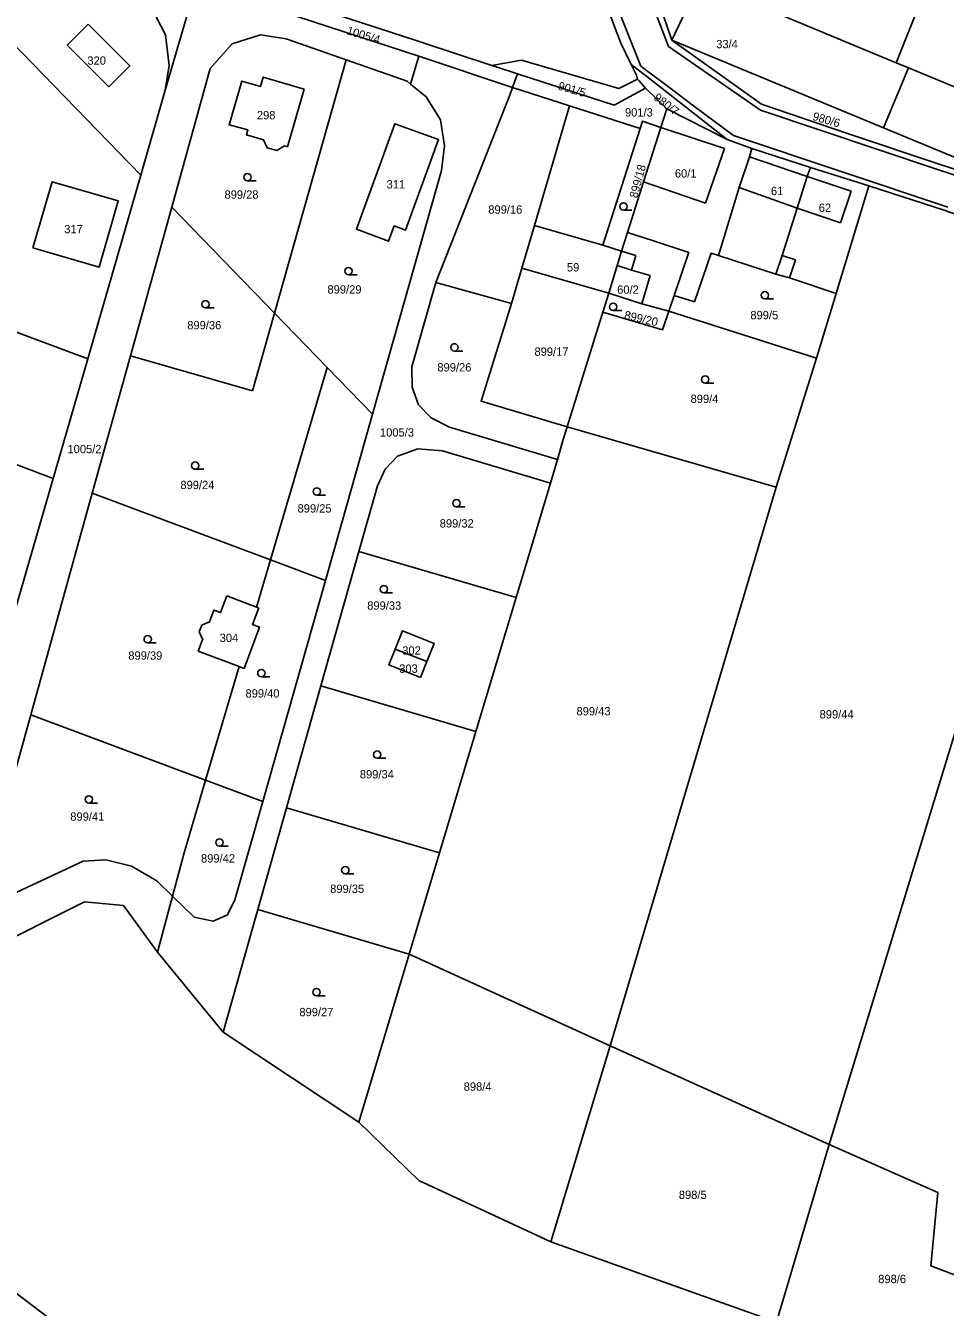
# Model space of a CAD drawing. Extents: x -7483133 to -743169, y -11317770 to -1127091.
# Drawn here: x -751107.9 to -750919.9, y -1131658.7 to -1131396.7 of the extents above; entities that cross this region are included whole.
import ezdxf

# ---------------------------------------------------------------- set-up
doc = ezdxf.new("R2010")
doc.units = 0
for name, color, linetype in [('Hranice parcel', 7, 'Continuous'), ('Parcelní čísla', 7, 'Continuous'), ('Vnitřní kresba', 7, 'Continuous'), ('Značky kultur', 7, 'Continuous')]:
    doc.layers.add(name, color=color, linetype=linetype)

msp = doc.modelspace()

# ---------------------------------------------------------------- linework, layer by layer
at = {"layer": 'Hranice parcel'}
for p, q in [((-751079.34, -1131409.92), (-751073.02, -1131388.06)), ((-751027.54, -1131402.97), (-751073.02, -1131388.06)), ((-750977.67, -1131394.32), (-750975.81, -1131399.68)), ((-750975.81, -1131399.68), (-750932.55, -1131417.63)), ((-751057.01, -1131455.49), (-751042.36, -1131403.71)), ((-751029.21, -1131408.66), (-751027.54, -1131402.97)), ((-751008.4, -1131409.35), (-751027.54, -1131402.97)), ((-751012.62, -1131404.83), (-751006.56, -1131403.77)), ((-751007.4, -1131406.54), (-751008.4, -1131409.35)), ((-751084.36, -1131427.31), (-751079.34, -1131409.92)), ((-751029.21, -1131408.66), (-751026.02, -1131411.27)), ((-750996.76, -1131413.1), (-751008.4, -1131409.35)), ((-750976.88, -1131413.73), (-750981.24, -1131409.5)), ((-750982.32, -1131417.76), (-750996.76, -1131413.1)), ((-750976.88, -1131413.73), (-750978.05, -1131417.53)), ((-750964.51, -1131419.97), (-750976.88, -1131413.73)), ((-750932.55, -1131417.63), (-750894.41, -1131433.45)), ((-750959.45, -1131421.83), (-750964.51, -1131419.97)), ((-750947.47, -1131425.71), (-750959.45, -1131421.83)), ((-750935.55, -1131429.45), (-750947.47, -1131425.71)), ((-750942.27, -1131451.45), (-750935.55, -1131429.45)), ((-751086.46, -1131464.18), (-751078.03, -1131433.83)), ((-751078.03, -1131433.83), (-751057.01, -1131455.49)), ((-750984.91, -1131439.01), (-750986.13, -1131442.83)), ((-750966.26, -1131443.71), (-750954.56, -1131447.49)), ((-751008.61, -1131453.5), (-751006.51, -1131446.29)), ((-751006.51, -1131446.29), (-750988.71, -1131451.43)), ((-750943.7, -1131625.46), (-750888.52, -1131444.72)), ((-751024.06, -1131449.21), (-751028.96, -1131466.48)), ((-751024.06, -1131449.21), (-751008.61, -1131453.5)), ((-750989.96, -1131455.31), (-750988.71, -1131451.43)), ((-750976.43, -1131455.09), (-750975.33, -1131451.88)), ((-750946.27, -1131464.68), (-750942.27, -1131451.45)), ((-751121.03, -1131455.15), (-751095.19, -1131464.83)), ((-750946.27, -1131464.68), (-750976.43, -1131455.09)), ((-751057.01, -1131455.49), (-751061.5, -1131471.37)), ((-751046.26, -1131466.58), (-751057.01, -1131455.49)), ((-750989.96, -1131455.31), (-750997.19, -1131478.72)), ((-751095.19, -1131464.83), (-751102.25, -1131489.28)), ((-751086.46, -1131464.18), (-751094.26, -1131492.28)), ((-751061.5, -1131471.37), (-751086.46, -1131464.18)), ((-750954.52, -1131491.04), (-750946.27, -1131464.68)), ((-751057.84, -1131505.93), (-751046.26, -1131466.58)), ((-751037, -1131476.13), (-751046.26, -1131466.58)), ((-751046.62, -1131510.13), (-751037, -1131476.13)), ((-750997.19, -1131478.72), (-750954.52, -1131491.04)), ((-751102.25, -1131489.28), (-751128.07, -1131479.61)), ((-751000.64, -1131490.21), (-750999.2, -1131485.42)), ((-751112.34, -1131524.21), (-751102.25, -1131489.28)), ((-751039.77, -1131504.19), (-751035.98, -1131490.76)), ((-751007.66, -1131513.63), (-751000.64, -1131490.21)), ((-750988.44, -1131605.26), (-750954.52, -1131491.04)), ((-751106.84, -1131537.6), (-751094.26, -1131492.28)), ((-751094.26, -1131492.28), (-751057.84, -1131505.93)), ((-751047.54, -1131531.7), (-751039.77, -1131504.19)), ((-751039.77, -1131504.19), (-751007.66, -1131513.63)), ((-751060.67, -1131515.57), (-751057.84, -1131505.93)), ((-751057.84, -1131505.93), (-751046.62, -1131510.13)), ((-751046.62, -1131510.13), (-751059.42, -1131555.35)), ((-751066.76, -1131513.28), (-751060.67, -1131515.57)), ((-751015.87, -1131541), (-751007.66, -1131513.63)), ((-751060.67, -1131515.57), (-751060.21, -1131515.74)), ((-751064.25, -1131527.72), (-751072.59, -1131524.6)), ((-751032.36, -1131524.15), (-751025.91, -1131526.72)), ((-751071.09, -1131550.98), (-751064.25, -1131527.72)), ((-751063.23, -1131528.1), (-751064.25, -1131527.72)), ((-751054.59, -1131556.64), (-751047.54, -1131531.7)), ((-751047.54, -1131531.7), (-751015.87, -1131541)), ((-751106.84, -1131537.6), (-751071.09, -1131550.98)), ((-751023.31, -1131565.83), (-751015.87, -1131541)), ((-751071.09, -1131550.98), (-751059.42, -1131555.35)), ((-751060.46, -1131577.42), (-751054.59, -1131556.64)), ((-751054.59, -1131556.64), (-751023.31, -1131565.83)), ((-751029.52, -1131586.51), (-751023.31, -1131565.83)), ((-751080.96, -1131586.15), (-751077.85, -1131574.67)), ((-751060.46, -1131577.42), (-751067.53, -1131602.46)), ((-751029.52, -1131586.51), (-751060.46, -1131577.42)), ((-751067.53, -1131602.46), (-751080.96, -1131586.15)), ((-751039.82, -1131620.88), (-751029.52, -1131586.51)), ((-750988.44, -1131605.26), (-751029.52, -1131586.51)), ((-751039.82, -1131620.88), (-751067.53, -1131602.46)), ((-751000.53, -1131645.34), (-750988.44, -1131605.26)), ((-750943.7, -1131625.46), (-750988.44, -1131605.26)), ((-750954.43, -1131661.73), (-750943.7, -1131625.46)), ((-750954.43, -1131661.73), (-751000.53, -1131645.34))]:
    msp.add_line(p, q, dxfattribs=at)
for points in [[(-750984.13, -1131404.64), (-750986.25, -1131400.3), (-751009.6, -1131338.57)], [(-751079.34, -1131409.92), (-751078.57, -1131404.84), (-751079.31, -1131398.59), (-751082.21, -1131392.91), (-751087.5, -1131388.18), (-751149.92, -1131356.39), (-751153.5, -1131356.01)], [(-750920.41, -1131380.22), (-750929.97, -1131404.28), (-750927.44, -1131405.33), (-750932.55, -1131417.63)], [(-751072.1, -1131385.39), (-751027.88, -1131399.84), (-751026.87, -1131400.17), (-751012.62, -1131404.83)], [(-751095.07, -1131396.41), (-751086.58, -1131404.94), (-751090.88, -1131409.21), (-751099.38, -1131400.67), (-751095.07, -1131396.41)], [(-751112.58, -1131398.2), (-751108.68, -1131402.23), (-751084.36, -1131427.31)], [(-751042.36, -1131403.71), (-751054.63, -1131399.4), (-751059.87, -1131398.6), (-751065.69, -1131400.42), (-751070.16, -1131405.5), (-751078.03, -1131433.83)], [(-750894.41, -1131433.45), (-750920.38, -1131425.31), (-750939.71, -1131418.8), (-750957.49, -1131412.77), (-750975.81, -1131399.68)], [(-751042.36, -1131403.71), (-751029.92, -1131408.08), (-751029.21, -1131408.66)], [(-751012.62, -1131404.83), (-751011.5, -1131405.2), (-751007.4, -1131406.54)], [(-751006.56, -1131403.77), (-750986.67, -1131409.56), (-750982.85, -1131407.64)], [(-750982.85, -1131407.64), (-750983.06, -1131406.82), (-750984.13, -1131404.64)], [(-750984.13, -1131404.64), (-750981.74, -1131406.51), (-750981.3, -1131406.85), (-750964.51, -1131419.97)], [(-751050.93, -1131409.72), (-751054.37, -1131421.46), (-751055.01, -1131421.27), (-751056.58, -1131422.26), (-751058.5, -1131421.71), (-751059.24, -1131420.05), (-751062.77, -1131419.02), (-751062.49, -1131418.04), (-751066.31, -1131416.96), (-751063.73, -1131408.09), (-751059.9, -1131409.18), (-751059.33, -1131407.22), (-751050.93, -1131409.72)], [(-750981.24, -1131409.5), (-750987.61, -1131413), (-751007.4, -1131406.54)], [(-750982.85, -1131407.64), (-750982.53, -1131408.01), (-750981.24, -1131409.5)], [(-751008.4, -1131409.35), (-751008.89, -1131410.74), (-751024.06, -1131449.21)], [(-751026.02, -1131411.27), (-751023.12, -1131415.94), (-751022.3, -1131421.26), (-751022.89, -1131426.29), (-751037, -1131476.13)], [(-750996.76, -1131413.1), (-751003.92, -1131437.58), (-751006.51, -1131446.29)], [(-751032.6, -1131437.65), (-751033.72, -1131440.78), (-751040.28, -1131438.34), (-751032.46, -1131416.75), (-751023.52, -1131419.98), (-751030.22, -1131438.54), (-751032.6, -1131437.65)], [(-750986.13, -1131442.83), (-750989.96, -1131441.61), (-750982.32, -1131417.76)], [(-750978.05, -1131417.53), (-750981.61, -1131428.65), (-750984.91, -1131439.01)], [(-750978.05, -1131417.53), (-750981.84, -1131416.27), (-750982.32, -1131417.76)], [(-750966.26, -1131443.71), (-750962.1, -1131429.8), (-750959.97, -1131423.55), (-750959.45, -1131421.83)], [(-750954.56, -1131447.49), (-750953.3, -1131443.69), (-750950.24, -1131434.01), (-750948.14, -1131427.56), (-750947.47, -1131425.71)], [(-751106.39, -1131442.16), (-751102.48, -1131428.64), (-751088.96, -1131432.55), (-751092.87, -1131446.07), (-751106.39, -1131442.16)], [(-751084.36, -1131427.31), (-751094.92, -1131463.9), (-751095.19, -1131464.83)], [(-750935.55, -1131429.45), (-750919.74, -1131434.58), (-750919.26, -1131434.74), (-750888.52, -1131444.72)], [(-750984.91, -1131439.01), (-750979.6, -1131440.73), (-750972.38, -1131443.07), (-750972.51, -1131443.45), (-750975.33, -1131451.88)], [(-750988.71, -1131451.43), (-750987.03, -1131445.76), (-750986.13, -1131442.83)], [(-750975.33, -1131451.88), (-750971.22, -1131453.14), (-750967.79, -1131443.22), (-750966.26, -1131443.71)], [(-750954.56, -1131447.49), (-750951.8, -1131448.27), (-750942.27, -1131451.45)], [(-750988.71, -1131451.43), (-750981.99, -1131453.55), (-750976.43, -1131455.09)], [(-751008.61, -1131453.5), (-751014.8, -1131473.49), (-750997.19, -1131478.72)], [(-750976.43, -1131455.09), (-750977.75, -1131458.88), (-750989.96, -1131455.31)], [(-751028.96, -1131466.48), (-751028.9, -1131470.65), (-751027.6, -1131474.24), (-751024.98, -1131476.86), (-751021.24, -1131478.82), (-750999.2, -1131485.42)], [(-750999.2, -1131485.42), (-750998.02, -1131481.29), (-750997.19, -1131478.72)], [(-751035.98, -1131490.76), (-751034.44, -1131487.38), (-751031.87, -1131484.73), (-751027.72, -1131483.19), (-751022.67, -1131483.61), (-751000.64, -1131490.21)], [(-751072.59, -1131524.6), (-751071.65, -1131522.08), (-751071.8, -1131522.02), (-751072.4, -1131520.65), (-751071.89, -1131519.25), (-751070.54, -1131518.64), (-751070.39, -1131518.71), (-751069.44, -1131516.18), (-751068.04, -1131516.7), (-751066.76, -1131513.28)], [(-751060.21, -1131515.74), (-751061.49, -1131519.15), (-751060.08, -1131519.68), (-751063.23, -1131528.1)], [(-751032.36, -1131524.15), (-751030.89, -1131520.44), (-751024.42, -1131523), (-751025.91, -1131526.72)], [(-751025.91, -1131526.72), (-751027.19, -1131529.95), (-751033.65, -1131527.38), (-751032.36, -1131524.15)], [(-751077.85, -1131574.67), (-751081.07, -1131571.51), (-751086.27, -1131568.56), (-751091.47, -1131567.23), (-751096.15, -1131567.52), (-751109.8, -1131573.95), (-751112.57, -1131574.29), (-751114.59, -1131573.08), (-751115.53, -1131571.46), (-751115.66, -1131569.38), (-751106.84, -1131537.6)], [(-751077.85, -1131574.67), (-751075.45, -1131565.8), (-751071.09, -1131550.98)], [(-751059.42, -1131555.35), (-751065.11, -1131575.44), (-751066.61, -1131578.46), (-751069.58, -1131579.75), (-751073.46, -1131578.98), (-751077.85, -1131574.67)], [(-751323.82, -1131561.58), (-751272.93, -1131567.59), (-751244.2, -1131610.68), (-751196.7, -1131636.78), (-751122.71, -1131646.1), (-751053.46, -1131698.72), (-751030.73, -1131701.58), (-751004.59, -1131712.2), (-750945.06, -1131720.15), (-750880.97, -1131755.87), (-750806.03, -1131757.06), (-750782.41, -1131781.2), (-750766.57, -1131788.17), (-750742.06, -1131786.93), (-750740.2, -1131775.46), (-750718.74, -1131766.85), (-750667.05, -1131813.02), (-750592.71, -1131860.77), (-750588.08, -1131875.75)], [(-751080.96, -1131586.15), (-751087.91, -1131576.56), (-751095.84, -1131575.81), (-751116.68, -1131586.24), (-751130.03, -1131585.48)], [(-751000.53, -1131645.34), (-751027.52, -1131632.8), (-751039.82, -1131620.88)], [(-750906.83, -1131656.39), (-750922.88, -1131650.23), (-750921.5, -1131635.24), (-750943.7, -1131625.46)]]:
    msp.add_lwpolyline(points, dxfattribs=at)
at = {"layer": 'Vnitřní kresba'}
for p, q in [((-750982.17, -1131405), (-751008.59, -1131338.48)), ((-750976.54, -1131400.97), (-751000.12, -1131338.48)), ((-750975.81, -1131399.68), (-750960.5, -1131367.4)), ((-750929.97, -1131404.28), (-750959.85, -1131391.88)), ((-750957.73, -1131413.99), (-750976.54, -1131400.97)), ((-750980.74, -1131406.07), (-750982.17, -1131405)), ((-750896.95, -1131417.98), (-750927.44, -1131405.33)), ((-750980.29, -1131406.4), (-750980.74, -1131406.07)), ((-750976.52, -1131409.22), (-750980.29, -1131406.4)), ((-750971.37, -1131413.08), (-750976.52, -1131409.22)), ((-750963.22, -1131419.19), (-750971.37, -1131413.08)), ((-750921.32, -1131426.22), (-750957.73, -1131413.99)), ((-750965.09, -1131421.84), (-750978.05, -1131417.53)), ((-750963.22, -1131419.19), (-750919.46, -1131433.85)), ((-750965.09, -1131421.84), (-750968.93, -1131432.99)), ((-750959.97, -1131423.55), (-750948.14, -1131427.56)), ((-750824.74, -1131457.49), (-750921.32, -1131426.22)), ((-750968.93, -1131432.99), (-750981.61, -1131428.65)), ((-750948.14, -1131427.56), (-750939.21, -1131430.52)), ((-750950.24, -1131434.01), (-750962.1, -1131429.8)), ((-750939.21, -1131430.52), (-750941.38, -1131437)), ((-750941.38, -1131437), (-750950.24, -1131434.01)), ((-750989.96, -1131441.61), (-751003.92, -1131437.58)), ((-750986.13, -1131442.83), (-750983.21, -1131443.7)), ((-750983.21, -1131443.7), (-750984.09, -1131446.71)), ((-750953.3, -1131443.69), (-750950.54, -1131444.59)), ((-750950.54, -1131444.59), (-750951.8, -1131448.27)), ((-750984.09, -1131446.71), (-750987.03, -1131445.76)), ((-750984.09, -1131446.71), (-750980.27, -1131447.76)), ((-750981.99, -1131453.55), (-750980.27, -1131447.76))]:
    msp.add_line(p, q, dxfattribs=at)
at = {"layer": 'Značky kultur'}
for p, q in [((-751062.54, -1131428.44), (-751060.79, -1131428.44)), ((-750985.72, -1131434.43), (-750983.97, -1131434.43)), ((-751041.91, -1131447.63), (-751040.16, -1131447.63)), ((-751071.12, -1131454.42), (-751069.37, -1131454.42)), ((-750987.83, -1131454.94), (-750986.08, -1131454.94)), ((-750956.82, -1131452.58), (-750955.07, -1131452.58)), ((-751020.26, -1131463.23), (-751018.51, -1131463.23)), ((-750969.02, -1131469.79), (-750967.27, -1131469.79)), ((-751073.24, -1131487.41), (-751071.49, -1131487.41)), ((-751048.37, -1131492.7), (-751046.62, -1131492.7)), ((-751019.85, -1131495.09), (-751018.1, -1131495.09)), ((-751034.68, -1131512.68), (-751032.93, -1131512.68)), ((-751082.94, -1131522.9), (-751081.19, -1131522.9)), ((-751059.71, -1131529.83), (-751057.96, -1131529.83)), ((-751036.05, -1131546.48), (-751034.3, -1131546.48)), ((-751094.97, -1131555.64), (-751093.22, -1131555.64)), ((-751068.26, -1131564.46), (-751066.51, -1131564.46)), ((-751042.55, -1131570.12), (-751040.8, -1131570.12)), ((-751048.44, -1131595.04), (-751046.69, -1131595.04))]:
    msp.add_line(p, q, dxfattribs=at)
for centre in [(-751062.54, -1131427.69), (-750985.72, -1131433.68), (-751041.91, -1131446.88), (-750956.82, -1131451.83), (-751071.12, -1131453.67), (-750987.83, -1131454.19), (-751020.26, -1131462.48), (-750969.02, -1131469.04), (-751073.24, -1131486.66), (-751048.37, -1131491.95), (-751019.85, -1131494.34), (-751034.68, -1131511.93), (-751082.94, -1131522.15), (-751059.71, -1131529.08), (-751036.05, -1131545.73), (-751094.97, -1131554.89), (-751068.26, -1131563.71), (-751042.55, -1131569.37), (-751048.44, -1131594.29)]:
    msp.add_circle(centre, 0.75, dxfattribs=at)

# ---------------------------------------------------------------- texts
at = {"layer": 'Parcelní čísla'}
for s, rotation, p in [('1005/4', 343, (-751042.4, -1131398.42)), ('901/5', 344, (-750999.19, -1131409.75)), ('980/7', 322, (-750979.69, -1131411.7)), ('980/6', 344, (-750947.2, -1131415.97)), ('899/18', 75, (-750982.89, -1131432.09)), ('899/20', 347, (-750985.66, -1131456.62))]:
    msp.add_text(s, height=1.7, rotation=rotation, dxfattribs=at).set_placement(p)
for s, p in [('33/4', (-750966.76, -1131401.33)), ('320', (-751095.26, -1131404.7)), ('298', (-751060.62, -1131415.85)), ('901/3', (-750985.41, -1131415.29)), ('60/1', (-750975.21, -1131427.77)), ('311', (-751034.12, -1131429.99)), ('899/28', (-751067.24, -1131432.09)), ('61', (-750955.58, -1131431.36)), ('899/16', (-751013.34, -1131435.15)), ('62', (-750945.8, -1131434.78)), ('317', (-751099.99, -1131439.15)), ('59', (-750997.27, -1131446.96)), ('899/29', (-751046.2, -1131451.48)), ('60/2', (-750987, -1131451.52)), ('899/5', (-750959.78, -1131456.73)), ('899/36', (-751074.85, -1131458.79)), ('899/17', (-751003.9, -1131464.2)), ('899/26', (-751023.74, -1131467.41)), ('899/4', (-750972, -1131473.85)), ('1005/3', (-751035.47, -1131480.72)), ('1005/2', (-751099.33, -1131484.12)), ('899/24', (-751076.25, -1131491.45)), ('899/25', (-751052.31, -1131496.25)), ('899/32', (-751023.26, -1131499.31)), ('899/33', (-751038.08, -1131516.11)), ('304', (-751068.23, -1131522.71)), ('899/39', (-751086.9, -1131526.33)), ('302', (-751030.92, -1131525.3)), ('303', (-751031.54, -1131529.01)), ('899/40', (-751062.95, -1131534.07)), ('899/43', (-750995.31, -1131537.71)), ('899/44', (-750945.63, -1131538.34)), ('899/34', (-751039.59, -1131550.6)), ('899/41', (-751098.75, -1131559.25)), ('899/42', (-751072.04, -1131567.8)), ('899/35', (-751045.65, -1131574.01)), ('899/27', (-751051.94, -1131599.21)), ('898/4', (-751018.36, -1131614.45)), ('898/5', (-750974.4, -1131636.57)), ('898/6', (-750933.66, -1131653.78))]:
    msp.add_text(s, height=1.7, dxfattribs=at).set_placement(p)

doc.saveas('drawing.dxf')
